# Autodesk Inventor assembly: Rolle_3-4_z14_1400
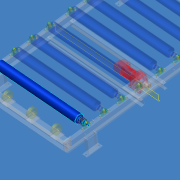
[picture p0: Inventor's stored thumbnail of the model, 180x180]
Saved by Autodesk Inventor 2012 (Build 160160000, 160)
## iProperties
Company: CAD-Verlag
Created: 2004-09
Part Number: Rolle_3-4_z14_1400
Document SubType Name: Assembly
Designer: Greiling
Manufacturer: Standard
Standards Organization: Custom
Control State: 0
Master: False
Checked Out: False
Shininess: 64.0
Length Units: 11269
Angle Units: 11279
Time Units: 11290
Mass Units: 11283
Length Display Precision: 3
Angle Display Precision: 2
Compacted: True
Density: 0.0
Volumn: 0.0
Area: 0.0
PropertySet Name: Model Information
Author: Jürgen Kronas
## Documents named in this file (3)
- C:\DemoDaten2012\CAD Daten\Daten Vault 2012 Inventor\Kapitel 6\6.4\Rollenbahn\Rollenbahn 1400\Rolle_3-4_z14_1400.iam
- C:\DemoDaten2012\CAD Daten\Daten Vault 2012 Inventor\Kapitel 6\6.4\Rollenbahn\Rollenbahn 1400\Rolle_3-4_z14_1400.ipt
- C:\DemoDaten2012\CAD Daten\Daten Vault 2012 Inventor\Kapitel 6\6.4\Rollenbahn\Rollenbahn 1400\3_4_z14.iam
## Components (3 placed, 2 different names)
1. Rolle_3-4_z14_1400:1 — Passend:1
2. 3_4_z14:1 [sub-assembly] — Passend:1
3. 3_4_z14:2 [sub-assembly]
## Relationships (1: Mate 1)
- Passend:1 [Mate]: Rolle_3-4_z14_1400:1 ↔ 3_4_z14:1
